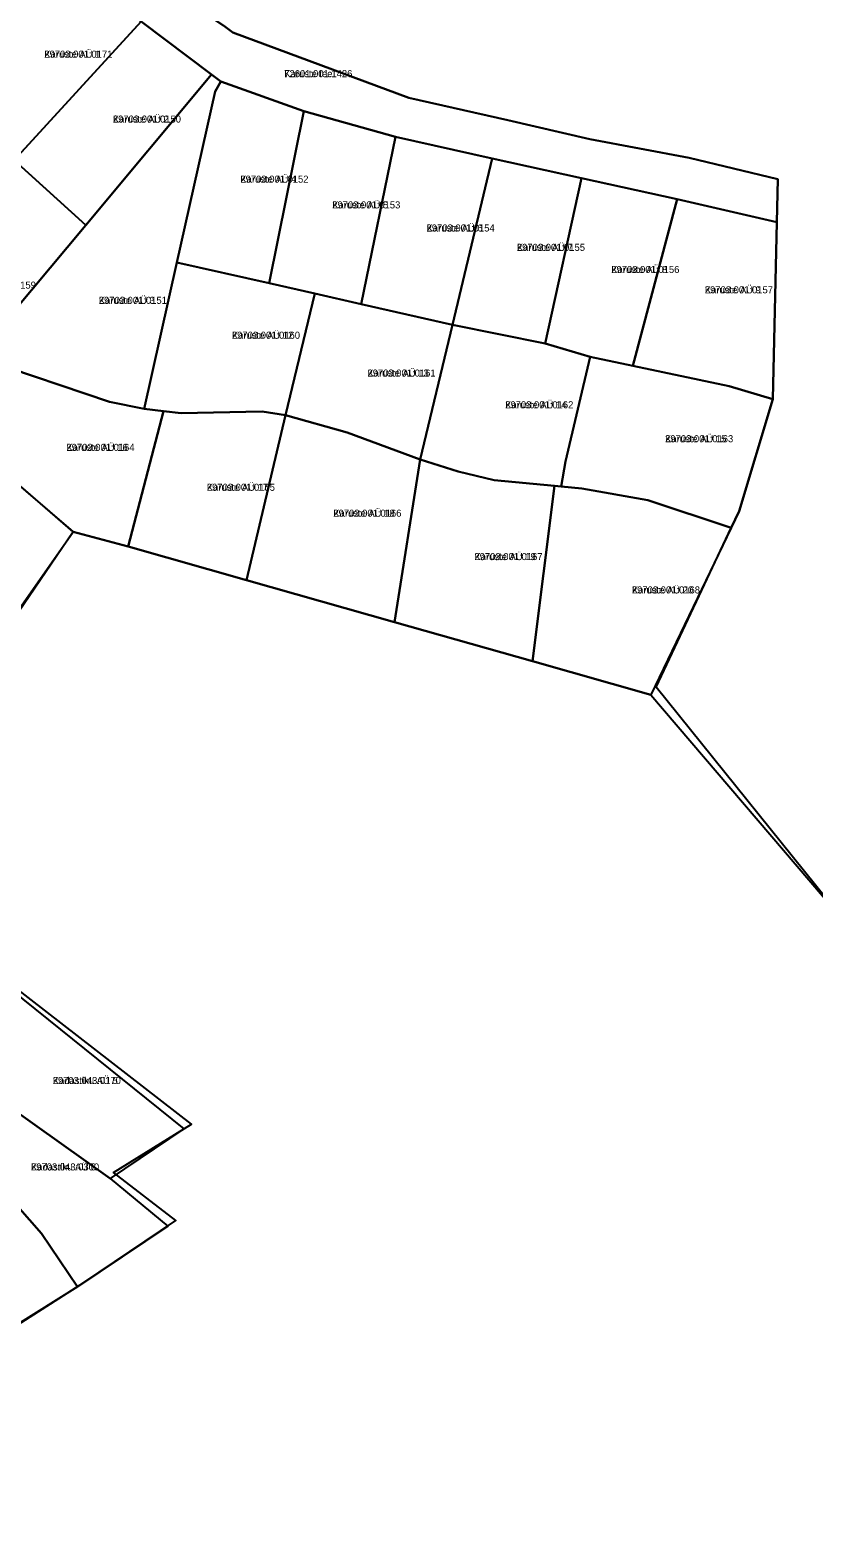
# Model space of a CAD drawing. Extents: x 504287 to 537970, y 6539941 to 6586214.
# Drawn here: x 519751.5 to 519918.3, y 6560333.9 to 6560654.7 of the extents above; entities that cross this region are included whole.
import ezdxf

# ---------------------------------------------------------------- set-up
doc = ezdxf.new("R2010")
doc.units = 0
for name, color, linetype in [('L_AADRESS', 7, 'Continuous'), ('PIIR', 7, 'Continuous'), ('TUNNUS', 7, 'Continuous')]:
    doc.layers.add(name, color=color, linetype=linetype)

msp = doc.modelspace()

# ---------------------------------------------------------------- linework, layer by layer
at = {"layer": 'PIIR'}
for points in [[(519910.5, 6560613.82), (519889.28, 6560618.69), (519868.87, 6560623.19), (519849.83, 6560627.36), (519829.26, 6560631.94), (519809.76, 6560637.42), (519792.1, 6560643.72), (519790.1, 6560645.25), (519775.14, 6560656.47), (519758.97, 6560668.59), (519767.85, 6560675.47), (519780.72, 6560663.62), (519792.68, 6560655.64), (519794.67, 6560654.16), (519832.1, 6560640.27), (519853.19, 6560635.54), (519870.68, 6560631.48), (519891.82, 6560627.49), (519910.69, 6560622.93)], [(519758.97, 6560668.59), (519775.14, 6560656.47), (519748.13, 6560626.98), (519733.89, 6560640.72)], [(519775.14, 6560656.47), (519790.1, 6560645.25), (519763.37, 6560613.2), (519748.13, 6560626.98)], [(519790.1, 6560645.25), (519792.1, 6560643.72), (519790.9, 6560641.63), (519782.76, 6560605.26), (519775.79, 6560574.07), (519768.41, 6560575.6), (519741.84, 6560584.51), (519740.15, 6560585.49), (519763.37, 6560613.2)], [(519792.1, 6560643.72), (519809.76, 6560637.42), (519802.36, 6560600.8), (519782.76, 6560605.26), (519790.9, 6560641.63)], [(519809.76, 6560637.42), (519829.26, 6560631.94), (519821.97, 6560596.34), (519812.08, 6560598.6), (519802.36, 6560600.8)], [(519829.26, 6560631.94), (519849.83, 6560627.36), (519841.4, 6560591.93), (519821.97, 6560596.34)], [(519849.83, 6560627.36), (519868.87, 6560623.19), (519861.16, 6560588.01), (519841.4, 6560591.93)], [(519748.13, 6560626.98), (519763.37, 6560613.2), (519740.15, 6560585.49), (519730.65, 6560573.89), (519714.73, 6560587.31), (519713.09, 6560588.78)], [(519868.87, 6560623.19), (519889.28, 6560618.69), (519879.79, 6560583.21), (519870.71, 6560585.17), (519861.16, 6560588.01)], [(519889.28, 6560618.69), (519910.5, 6560613.82), (519909.64, 6560576.13), (519900.29, 6560578.93), (519879.79, 6560583.21)], [(519782.76, 6560605.26), (519802.36, 6560600.8), (519812.08, 6560598.6), (519805.9, 6560572.73), (519800.91, 6560573.54), (519783.67, 6560573.18), (519779.93, 6560573.6), (519775.79, 6560574.07)], [(519696.51, 6560602.52), (519714.73, 6560587.31), (519760.67, 6560547.92), (519749.01, 6560530.86), (519740.41, 6560536.98), (519732.08, 6560543.74), (519738.31, 6560551.32), (519710.34, 6560574.02), (519704.32, 6560579.41), (519696.48, 6560566.19), (519671.78, 6560584.27), (519676.22, 6560591.64)], [(519812.08, 6560598.6), (519821.97, 6560596.34), (519841.4, 6560591.93), (519834.57, 6560563.32), (519819, 6560569.09), (519805.9, 6560572.73)], [(519841.4, 6560591.93), (519861.16, 6560588.01), (519870.71, 6560585.17), (519865.51, 6560562.9), (519864.53, 6560557.59), (519863.15, 6560557.73), (519850.32, 6560558.93), (519842.65, 6560560.73), (519834.57, 6560563.32)], [(519740.15, 6560585.49), (519741.84, 6560584.51), (519768.41, 6560575.6), (519775.79, 6560574.07), (519779.93, 6560573.6), (519772.35, 6560544.8), (519760.67, 6560547.92), (519730.65, 6560573.89)], [(519865.51, 6560562.9), (519870.71, 6560585.17), (519879.79, 6560583.21), (519900.29, 6560578.93), (519909.64, 6560576.13), (519902.48, 6560552.29), (519900.75, 6560548.8), (519882.97, 6560554.67), (519868.94, 6560557.18), (519864.53, 6560557.59)], [(519779.93, 6560573.6), (519783.67, 6560573.18), (519800.91, 6560573.54), (519805.9, 6560572.73), (519797.54, 6560537.62), (519772.35, 6560544.8)], [(519805.9, 6560572.73), (519819, 6560569.09), (519834.57, 6560563.32), (519829.04, 6560528.69), (519797.54, 6560537.62)], [(519834.57, 6560563.32), (519842.65, 6560560.73), (519850.32, 6560558.93), (519863.15, 6560557.73), (519858.47, 6560520.41), (519829.04, 6560528.69)], [(519863.15, 6560557.73), (519864.53, 6560557.59), (519868.94, 6560557.18), (519882.97, 6560554.67), (519900.75, 6560548.8), (519883.63, 6560513.22), (519858.47, 6560520.41)], [(519747.37, 6560450.55), (519784.26, 6560420.94), (519768.54, 6560410.35), (519736.4, 6560433.16)], [(519731.22, 6560436.86), (519736.4, 6560433.16), (519768.54, 6560410.35), (519780.84, 6560400.25), (519761.57, 6560387.29), (519753.9, 6560398.64), (519748.82, 6560404.48), (519735.65, 6560413.14), (519728.07, 6560418.57), (519721.72, 6560422.92)], [(519721.72, 6560422.92), (519728.07, 6560418.57), (519735.65, 6560413.14), (519748.82, 6560404.48), (519753.9, 6560398.64), (519761.57, 6560387.29), (519735.51, 6560371.08), (519712.02, 6560408.73)]]:
    msp.add_lwpolyline(points, close=True, dxfattribs=at)
for points in [[(519926.01, 6560463.67), (519884.76, 6560514.86), (519900.75, 6560548.8), (519902.48, 6560552.29), (519909.64, 6560576.13), (519910.5, 6560613.82), (519910.69, 6560622.93), (519891.82, 6560627.49), (519870.68, 6560631.48), (519853.19, 6560635.54), (519832.1, 6560640.27), (519794.67, 6560654.16), (519792.68, 6560655.64)], [(519703.18, 6560322.99), (519713.19, 6560344.19), (519691.96, 6560356.34), (519698.12, 6560365.63), (519712.14, 6560374.97), (519724.32, 6560363.49), (519737.28, 6560371.88), (519762.93, 6560388.21), (519782.49, 6560401.44), (519769.22, 6560411.65), (519785.83, 6560421.92), (519748.28, 6560451.06), (519742.16, 6560456.22), (519722.85, 6560470.8), (519723.75, 6560493.59), (519749.63, 6560532.14), (519760.67, 6560547.92), (519772.35, 6560544.8), (519797.54, 6560537.62), (519829.04, 6560528.69), (519858.47, 6560520.41), (519883.63, 6560513.22), (519926.01, 6560463.67)]]:
    msp.add_lwpolyline(points, dxfattribs=at)

# ---------------------------------------------------------------- texts
at = {"layer": 'L_AADRESS'}
for s, p in [('Karuste AÜ 1', (519754.52, 6560648.8)), ('Karuste tee', (519805.6, 6560644.65)), ('Karuste AÜ 2', (519769.12, 6560634.99)), ('Karuste AÜ 4', (519796.26, 6560622.21)), ('Karuste AÜ 5', (519815.81, 6560616.73)), ('Karuste AÜ 6', (519835.9, 6560611.82)), ('Karuste AÜ 7', (519855.13, 6560607.7)), ('Karuste AÜ 8', (519875.22, 6560602.99)), ('Karuste AÜ 9', (519895.14, 6560598.67)), ('Karuste AÜ 3', (519766.12, 6560596.43)), ('Karuste AÜ 12', (519794.46, 6560589)), ('Karuste AÜ 13', (519823.32, 6560580.96)), ('Karuste AÜ 14', (519852.64, 6560574.21)), ('Karuste AÜ 16', (519759.23, 6560565.15)), ('Karuste AÜ 15', (519886.68, 6560566.99)), ('Karuste AÜ 17', (519789.12, 6560556.66)), ('Karuste AÜ 18', (519816.05, 6560551.14)), ('Karuste AÜ 19', (519846.09, 6560541.91)), ('Karuste AÜ 20', (519879.61, 6560534.82)), ('Kadastiku AÜ 5', (519756.32, 6560430.45)), ('Kadastiku AÜ 6', (519751.69, 6560412.07))]:
    msp.add_text(s, height=1.5, dxfattribs=at).set_placement(p)
at = {"layer": 'TUNNUS'}
for s, p in [('29703:001:0171', (519754.52, 6560648.8)), ('72601:001:1426', (519805.6, 6560644.65)), ('29703:001:0150', (519769.12, 6560634.99)), ('29703:001:0152', (519796.26, 6560622.21)), ('29703:001:0153', (519815.81, 6560616.73)), ('29703:001:0154', (519835.9, 6560611.82)), ('29703:001:0155', (519855.13, 6560607.7)), ('29703:001:0156', (519875.22, 6560602.99)), ('29703:001:0159', (519738.23, 6560599.67)), ('29703:001:0157', (519895.14, 6560598.67)), ('29703:001:0151', (519766.12, 6560596.43)), ('29703:001:0160', (519794.46, 6560589)), ('29703:001:0161', (519823.32, 6560580.96)), ('29703:001:0162', (519852.64, 6560574.21)), ('29703:001:0164', (519759.23, 6560565.15)), ('29703:001:0163', (519886.68, 6560566.99)), ('29703:001:0165', (519789.12, 6560556.66)), ('29703:001:0166', (519816.05, 6560551.14)), ('29703:001:0167', (519846.09, 6560541.91)), ('29703:001:0168', (519879.61, 6560534.82)), ('29703:043:0170', (519756.32, 6560430.45)), ('29703:043:0300', (519751.69, 6560412.07))]:
    msp.add_text(s, height=1.5, dxfattribs=at).set_placement(p)

doc.saveas('drawing.dxf')
